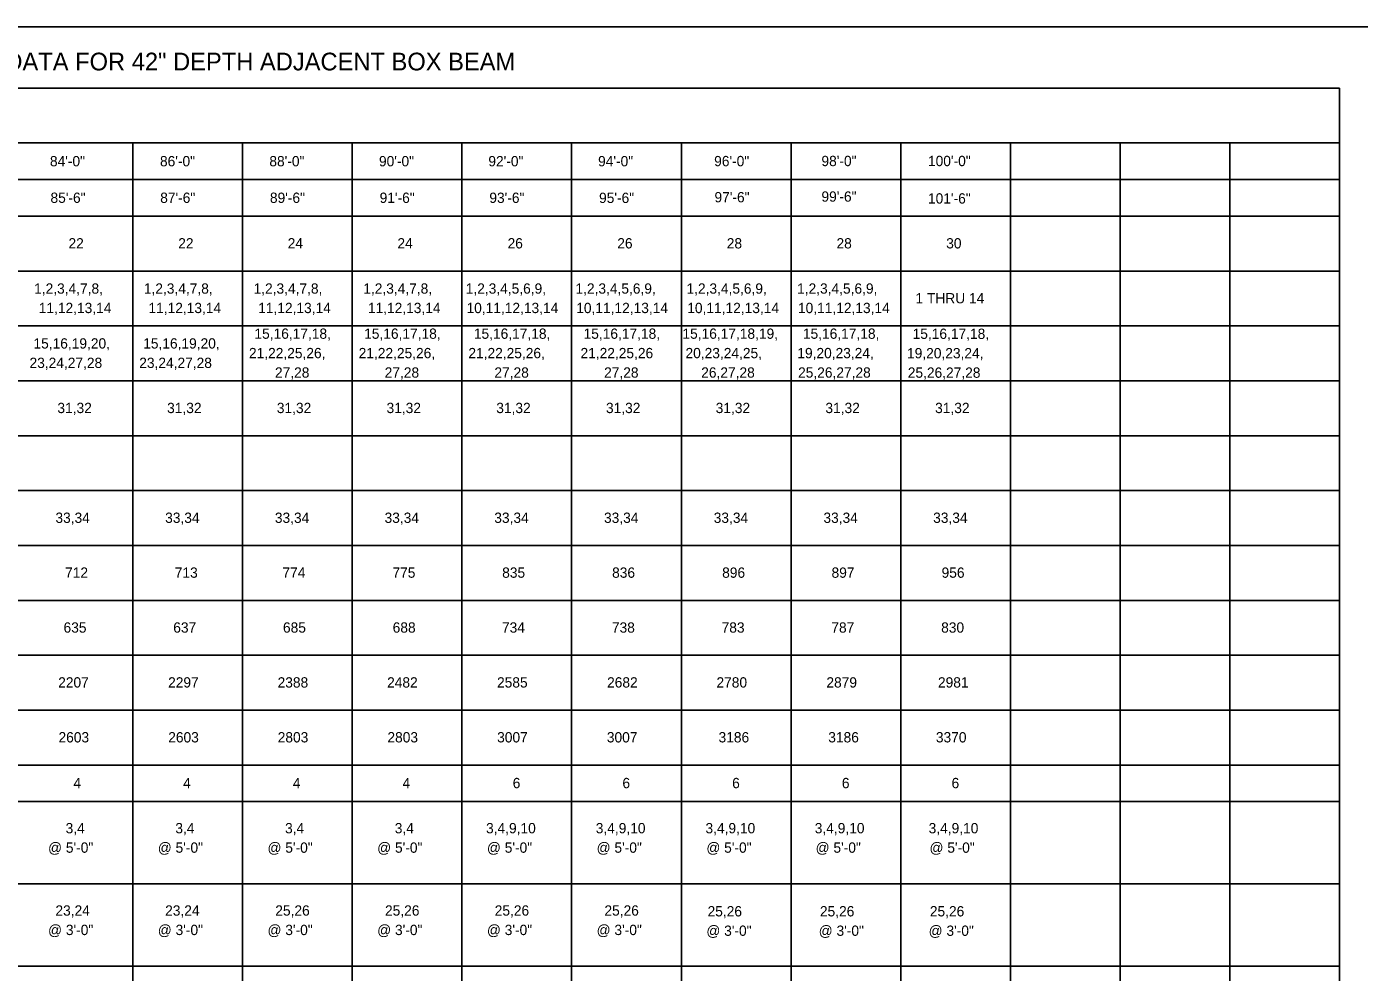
# Model space of a CAD drawing. Extents: x 762.3 to 790.4, y -1210.3 to -1192.2.
# Drawn here: x 772.12 to 784.27, y -1201.22 to -1192.61 of the extents above; entities that cross this region are included whole.
import ezdxf

# ---------------------------------------------------------------- set-up
doc = ezdxf.new("R2010")
doc.units = 0
doc.layers.add('Default', color=7, linetype='Continuous')

msp = doc.modelspace()

# ---------------------------------------------------------------- linework, layer by layer
at = {"layer": 'Default'}
for p, q in [((763.554, -1192.61), (789.954, -1192.61)), ((764.508, -1193.169), (784.091, -1193.169)), ((784.091, -1197.336), (784.091, -1193.169)), ((764.508, -1193.669), (784.091, -1193.669)), ((773.091, -1197.336), (773.091, -1193.669)), ((774.091, -1197.336), (774.091, -1193.669)), ((775.091, -1197.336), (775.091, -1193.669)), ((776.091, -1197.336), (776.091, -1193.669)), ((777.091, -1197.336), (777.091, -1193.669)), ((778.091, -1197.336), (778.091, -1193.669)), ((779.091, -1197.336), (779.091, -1193.669)), ((780.091, -1197.336), (780.091, -1193.669)), ((781.091, -1197.336), (781.091, -1193.669)), ((782.091, -1197.336), (782.091, -1193.669)), ((783.091, -1197.336), (783.091, -1193.669)), ((764.508, -1194.002), (784.091, -1194.002)), ((764.508, -1194.336), (784.091, -1194.336)), ((764.508, -1194.836), (784.091, -1194.836)), ((767.198, -1195.336), (784.091, -1195.336)), ((767.198, -1195.836), (784.091, -1195.836)), ((767.198, -1196.336), (784.091, -1196.336)), ((767.198, -1196.836), (784.091, -1196.836)), ((764.508, -1197.336), (784.091, -1197.336)), ((773.091, -1201.169), (773.091, -1197.336)), ((774.091, -1201.169), (774.091, -1197.336)), ((775.091, -1201.169), (775.091, -1197.336)), ((776.091, -1201.169), (776.091, -1197.336)), ((777.091, -1201.169), (777.091, -1197.336)), ((778.091, -1201.169), (778.091, -1197.336)), ((779.091, -1201.169), (779.091, -1197.336)), ((780.091, -1201.169), (780.091, -1197.336)), ((781.091, -1201.169), (781.091, -1197.336)), ((782.091, -1201.169), (782.091, -1197.336)), ((783.091, -1201.169), (783.091, -1197.336)), ((784.091, -1201.169), (784.091, -1197.336)), ((764.508, -1197.836), (784.091, -1197.836)), ((764.508, -1198.336), (784.091, -1198.336)), ((764.508, -1198.836), (784.091, -1198.836)), ((764.508, -1199.336), (784.091, -1199.336)), ((764.508, -1199.669), (784.091, -1199.669)), ((767.198, -1200.419), (784.091, -1200.419)), ((764.508, -1201.169), (784.091, -1201.169)), ((773.091, -1202.169), (773.091, -1201.169)), ((774.091, -1202.169), (774.091, -1201.169)), ((775.091, -1202.169), (775.091, -1201.169)), ((776.091, -1202.169), (776.091, -1201.169)), ((777.091, -1202.169), (777.091, -1201.169)), ((778.091, -1202.169), (778.091, -1201.169)), ((779.091, -1202.169), (779.091, -1201.169)), ((780.091, -1202.169), (780.091, -1201.169)), ((781.091, -1202.169), (781.091, -1201.169)), ((782.091, -1202.169), (782.091, -1201.169)), ((783.091, -1202.169), (783.091, -1201.169)), ((784.091, -1202.169), (784.091, -1201.169))]:
    msp.add_line(p, q, dxfattribs=at)

# ---------------------------------------------------------------- texts
for s, height, p in [('DESIGN DATA FOR 42" DEPTH ADJACENT BOX BEAM', 0.16146, (771.042, -1193.008)), ('84\'-0"', 0.0938, (772.336, -1193.882)), ('86\'-0"', 0.0938, (773.339, -1193.882)), ('88\'-0"', 0.0938, (774.336, -1193.882)), ('90\'-0"', 0.0938, (775.335, -1193.882)), ('92\'-0"', 0.0938, (776.332, -1193.882)), ('94\'-0"', 0.0938, (777.332, -1193.882)), ('96\'-0"', 0.0938, (778.39, -1193.881)), ('98\'-0"', 0.0938, (779.368, -1193.88)), ('100\'-0"', 0.0938, (780.339, -1193.88)), ('85\'-6"', 0.0938, (772.341, -1194.215)), ('87\'-6"', 0.0938, (773.341, -1194.215)), ('89\'-6"', 0.0938, (774.341, -1194.215)), ('91\'-6"', 0.0938, (775.341, -1194.215)), ('93\'-6"', 0.0938, (776.341, -1194.215)), ('95\'-6"', 0.0938, (777.341, -1194.216)), ('97\'-6"', 0.0938, (778.393, -1194.21)), ('99\'-6"', 0.0938, (779.368, -1194.204)), ('101\'-6"', 0.0938, (780.339, -1194.221)), ('22', 0.0938, (772.505, -1194.63)), ('22', 0.0938, (773.505, -1194.63)), ('24', 0.0938, (774.503, -1194.63)), ('24', 0.0938, (775.503, -1194.63)), ('26', 0.0938, (776.507, -1194.63)), ('26', 0.0938, (777.507, -1194.63)), ('28', 0.0938, (778.505, -1194.63)), ('28', 0.0938, (779.505, -1194.63)), ('30', 0.0938, (780.505, -1194.63)), ('1,2,3,4,7,8,', 0.09375, (772.192, -1195.042)), ('1,2,3,4,7,8,', 0.09375, (773.192, -1195.042)), ('1,2,3,4,7,8,', 0.09375, (774.192, -1195.042)), ('1,2,3,4,7,8,', 0.09375, (775.192, -1195.042)), ('1,2,3,4,5,6,9,', 0.09375, (776.126, -1195.042)), ('1,2,3,4,5,6,9,', 0.09375, (777.126, -1195.042)), ('1,2,3,4,5,6,9,', 0.09375, (778.138, -1195.042)), ('1,2,3,4,5,6,9,', 0.09375, (779.146, -1195.042)), ('11,12,13,14', 0.09375, (772.234, -1195.219)), ('11,12,13,14', 0.09375, (773.234, -1195.219)), ('11,12,13,14', 0.09375, (774.234, -1195.219)), ('11,12,13,14', 0.09375, (775.234, -1195.219)), ('10,11,12,13,14', 0.09375, (776.133, -1195.219)), ('10,11,12,13,14', 0.09375, (777.133, -1195.219)), ('10,11,12,13,14', 0.09375, (778.145, -1195.219)), ('10,11,12,13,14', 0.09375, (779.154, -1195.219)), ('1 THRU 14', 0.0938, (780.225, -1195.13)), ('15,16,17,18,', 0.09375, (774.2, -1195.453)), ('15,16,17,18,', 0.09375, (775.2, -1195.453)), ('15,16,17,18,', 0.09375, (776.2, -1195.453)), ('15,16,17,18,', 0.09375, (777.2, -1195.453)), ('15,16,17,18,19,', 0.09375, (778.101, -1195.453)), ('15,16,17,18,', 0.09375, (779.199, -1195.453)), ('15,16,17,18,', 0.09375, (780.199, -1195.454)), ('15,16,19,20,', 0.09375, (772.186, -1195.542)), ('15,16,19,20,', 0.09375, (773.186, -1195.542)), ('21,22,25,26,', 0.09375, (774.15, -1195.63)), ('21,22,25,26,', 0.09375, (775.15, -1195.63)), ('21,22,25,26,', 0.09375, (776.15, -1195.63)), ('21,22,25,26', 0.09375, (777.172, -1195.63)), ('20,23,24,25,', 0.09375, (778.129, -1195.63)), ('19,20,23,24,', 0.09375, (779.148, -1195.63)), ('19,20,23,24,', 0.09375, (780.148, -1195.631)), ('23,24,27,28', 0.09375, (772.15, -1195.719)), ('23,24,27,28', 0.09375, (773.15, -1195.719)), ('27,28', 0.0938, (774.387, -1195.807)), ('27,28', 0.0938, (775.387, -1195.807)), ('27,28', 0.0938, (776.387, -1195.807)), ('27,28', 0.0938, (777.387, -1195.807)), ('26,27,28', 0.0938, (778.272, -1195.807)), ('25,26,27,28', 0.09375, (779.155, -1195.807)), ('25,26,27,28', 0.09375, (780.155, -1195.808)), ('31,32', 0.0938, (772.404, -1196.13)), ('31,32', 0.0938, (773.404, -1196.13)), ('31,32', 0.0938, (774.404, -1196.13)), ('31,32', 0.0938, (775.404, -1196.13)), ('31,32', 0.0938, (776.404, -1196.13)), ('31,32', 0.0938, (777.404, -1196.13)), ('31,32', 0.0938, (778.404, -1196.13)), ('31,32', 0.0938, (779.404, -1196.13)), ('31,32', 0.0938, (780.404, -1196.13)), ('33,34', 0.0938, (772.386, -1197.13)), ('33,34', 0.0938, (773.386, -1197.13)), ('33,34', 0.0938, (774.386, -1197.13)), ('33,34', 0.0938, (775.386, -1197.13)), ('33,34', 0.0938, (776.386, -1197.13)), ('33,34', 0.0938, (777.386, -1197.13)), ('33,34', 0.0938, (778.386, -1197.13)), ('33,34', 0.0938, (779.386, -1197.13)), ('33,34', 0.0938, (780.386, -1197.13)), ('712', 0.0938, (772.474, -1197.63)), ('713', 0.0938, (773.474, -1197.63)), ('774', 0.0938, (774.455, -1197.63)), ('775', 0.0938, (775.458, -1197.63)), ('835', 0.0938, (776.458, -1197.63)), ('836', 0.0938, (777.46, -1197.63)), ('896', 0.0938, (778.463, -1197.63)), ('897', 0.0938, (779.46, -1197.63)), ('956', 0.0938, (780.463, -1197.63)), ('635', 0.0938, (772.46, -1198.13)), ('637', 0.0938, (773.46, -1198.13)), ('685', 0.0938, (774.46, -1198.13)), ('688', 0.0938, (775.46, -1198.13)), ('734', 0.0938, (776.456, -1198.13)), ('738', 0.0938, (777.458, -1198.13)), ('783', 0.0938, (778.458, -1198.13)), ('787', 0.0938, (779.458, -1198.13)), ('830', 0.0938, (780.459, -1198.13)), ('2207', 0.0938, (772.411, -1198.63)), ('2297', 0.0938, (773.413, -1198.63)), ('2388', 0.0938, (774.411, -1198.63)), ('2482', 0.0938, (775.409, -1198.63)), ('2585', 0.0938, (776.411, -1198.63)), ('2682', 0.0938, (777.414, -1198.63)), ('2780', 0.0938, (778.411, -1198.63)), ('2879', 0.0938, (779.413, -1198.63)), ('2981', 0.0938, (780.43, -1198.63)), ('2603', 0.0938, (772.414, -1199.13)), ('2603', 0.0938, (773.414, -1199.13)), ('2803', 0.0938, (774.412, -1199.13)), ('2803', 0.0938, (775.412, -1199.13)), ('3007', 0.0938, (776.412, -1199.13)), ('3007', 0.0938, (777.412, -1199.13)), ('3186', 0.0938, (778.43, -1199.13)), ('3186', 0.0938, (779.43, -1199.13)), ('3370', 0.0938, (780.411, -1199.13)), ('4', 0.0938, (772.55, -1199.547)), ('4', 0.0938, (773.55, -1199.547)), ('4', 0.0938, (774.55, -1199.547)), ('4', 0.0938, (775.55, -1199.547)), ('6', 0.0938, (776.554, -1199.547)), ('6', 0.0938, (777.554, -1199.547)), ('6', 0.0938, (778.554, -1199.547)), ('6', 0.0938, (779.554, -1199.547)), ('6', 0.0938, (780.554, -1199.547)), ('3,4', 0.0938, (772.479, -1199.958)), ('3,4', 0.0938, (773.479, -1199.958)), ('3,4', 0.0938, (774.479, -1199.958)), ('3,4', 0.0938, (775.479, -1199.958)), ('3,4,9,10', 0.0938, (776.311, -1199.958)), ('3,4,9,10', 0.0938, (777.311, -1199.958)), ('3,4,9,10', 0.0938, (778.311, -1199.958)), ('3,4,9,10', 0.0938, (779.307, -1199.958)), ('3,4,9,10', 0.0938, (780.345, -1199.958)), ('@ 5\'-0"', 0.0938, (772.319, -1200.135)), ('@ 5\'-0"', 0.0938, (773.319, -1200.135)), ('@ 5\'-0"', 0.0938, (774.319, -1200.135)), ('@ 5\'-0"', 0.0938, (775.319, -1200.135)), ('@ 5\'-0"', 0.0938, (776.319, -1200.135)), ('@ 5\'-0"', 0.0938, (777.319, -1200.135)), ('@ 5\'-0"', 0.0938, (778.319, -1200.135)), ('@ 5\'-0"', 0.0938, (779.315, -1200.135)), ('@ 5\'-0"', 0.0938, (780.353, -1200.135)), ('23,24', 0.0938, (772.386, -1200.708)), ('23,24', 0.0938, (773.386, -1200.708)), ('25,26', 0.0938, (774.39, -1200.708)), ('25,26', 0.0938, (775.39, -1200.708)), ('25,26', 0.0938, (776.39, -1200.708)), ('25,26', 0.0938, (777.39, -1200.708)), ('25,26 ', 0.0938, (778.33, -1200.715)), ('25,26 ', 0.0938, (779.354, -1200.715)), ('25,26 ', 0.0938, (780.356, -1200.715)), ('@ 3\'-0"', 0.0938, (772.319, -1200.885)), ('@ 3\'-0"', 0.0938, (773.319, -1200.885)), ('@ 3\'-0"', 0.0938, (774.319, -1200.885)), ('@ 3\'-0"', 0.0938, (775.319, -1200.885)), ('@ 3\'-0"', 0.0938, (776.319, -1200.885)), ('@ 3\'-0"', 0.0938, (777.319, -1200.885)), ('@ 3\'-0"', 0.0938, (778.319, -1200.892)), ('@ 3\'-0"', 0.0938, (779.343, -1200.892)), ('@ 3\'-0"', 0.0938, (780.345, -1200.892))]:
    msp.add_text(s, height=height, dxfattribs=at).set_placement(p)

doc.saveas('drawing.dxf')
